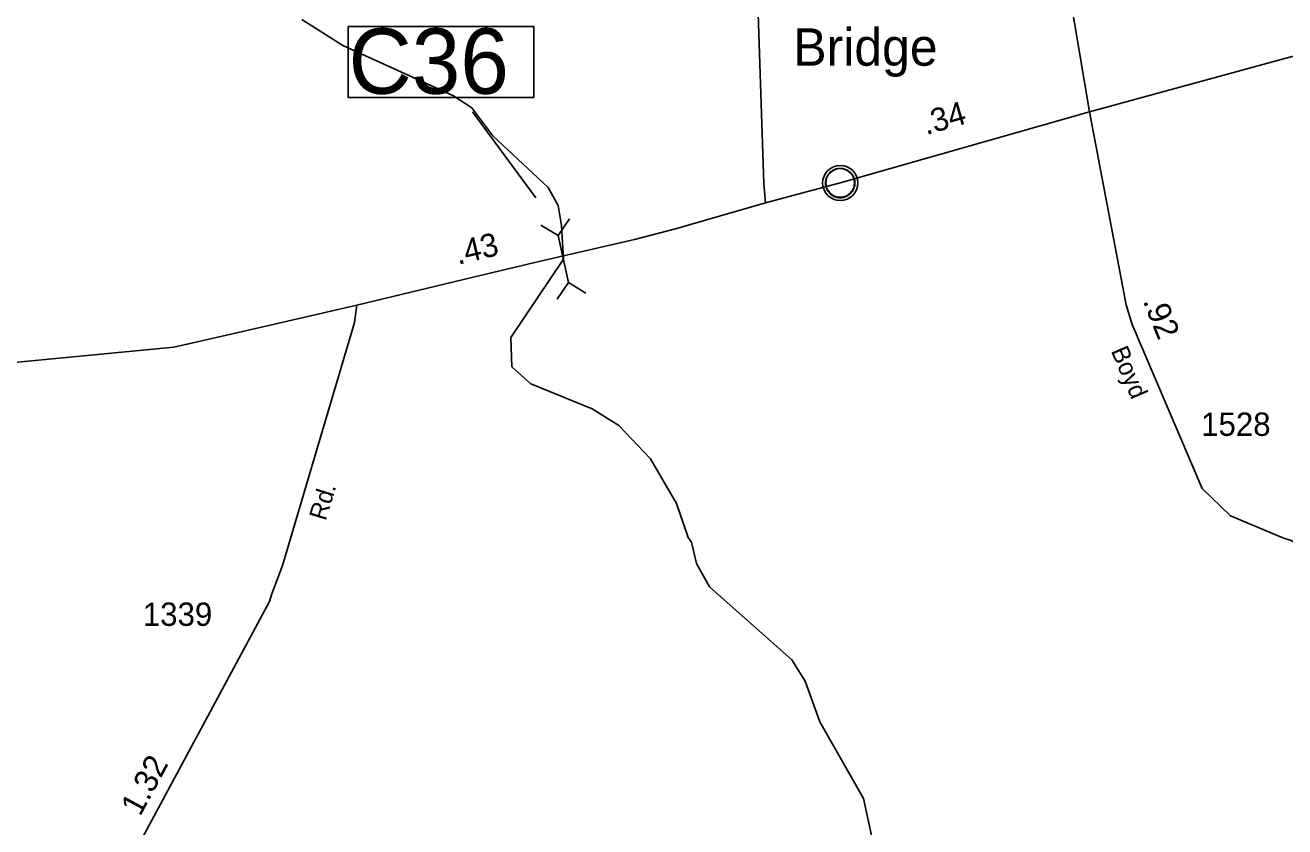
# Model space of a CAD drawing. Extents: x 2532689 to 2764727, y 536648 to 732970.
# Drawn here: x 2648911 to 2655658, y 649333 to 653624 of the extents above; entities that cross this region are included whole.
import ezdxf

# ---------------------------------------------------------------- set-up
doc = ezdxf.new("R2010")
doc.units = 0
for name, color, linetype in [('Exist Civil Demographics Community CELL', 7, 'Continuous'), ('Exist Civil Demographics Community Label', 7, 'Continuous'), ('Exist Hydrographic Creek Single Shore', 7, 'Continuous'), ('Exist Road Primary US Attributed', 7, 'Continuous'), ('Exist Road Primary US Mileage Hundredths English Label', 7, 'Continuous'), ('Exist Road Primary US Structure Culvert CELL', 7, 'Continuous'), ('Exist Road Primary US Structure Culvert Number Label', 7, 'Continuous'), ('Exist Road Secondary Mileage Hundredths English Label', 7, 'Continuous'), ('Exist Road Secondary Type 51 Attributed', 7, 'Continuous'), ('Exist Road Secondary Type 51 Label', 7, 'Continuous'), ('Exist Road Secondary Type 51 Number Label', 7, 'Continuous')]:
    doc.layers.add(name, color=color, linetype=linetype)

msp = doc.modelspace()

# ---------------------------------------------------------------- linework, layer by layer
at = {"layer": 'Exist Civil Demographics Community CELL'}
msp.add_lwpolyline([(2653199.2, 652792), (2653200.2, 652797.6), (2653201.9, 652804.2), (2653204.8, 652811.4), (2653207.8, 652817.1), (2653211.1, 652822.9), (2653214.9, 652828), (2653218.8, 652832.4), (2653223.4, 652836.9), (2653229, 652841.5), (2653234.4, 652845.2), (2653239.3, 652848.1), (2653244.3, 652850.5), (2653249.8, 652852.8), (2653255.4, 652854.6), (2653259.7, 652855.8), (2653264.6, 652856.5), (2653268.7, 652857.2), (2653275.1, 652857.5), (2653279.5, 652857.4), (2653285.2, 652857.1), (2653290.1, 652856.4), (2653295, 652855.4), (2653300, 652854), (2653305.2, 652852.1), (2653311.8, 652849.2), (2653318.1, 652845.7), (2653323.1, 652842.1), (2653328.3, 652838.1), (2653331.6, 652835), (2653335.7, 652830.6), (2653339.6, 652825.9), (2653342.7, 652821.3), (2653345.8, 652816.3), (2653348.3, 652811.1), (2653350.3, 652806.1), (2653351.9, 652801.1), (2653353.1, 652796.5), (2653354.2, 652790.5), (2653354.9, 652785.8), (2653355.1, 652779.8), (2653354.9, 652774), (2653354.4, 652768.3), (2653353.4, 652762.8), (2653351.8, 652756.6), (2653349.9, 652750.8), (2653347.6, 652745.7), (2653344.5, 652739.7), (2653341.2, 652734.4), (2653337.7, 652729.7), (2653333.5, 652725), (2653328.2, 652720), (2653323.2, 652715.9), (2653318.2, 652712.4), (2653313.8, 652709.9), (2653307, 652706.7), (2653299.9, 652704), (2653293.9, 652702.5), (2653287.3, 652701.2), (2653282.9, 652700.8), (2653278.4, 652700.5), (2653272.8, 652700.5), (2653268.6, 652700.9), (2653262.9, 652701.6), (2653257, 652703), (2653252.4, 652704.3), (2653247.2, 652706.1), (2653242.7, 652708.1), (2653238.7, 652710.4), (2653231.9, 652714.4), (2653226.3, 652718.7), (2653221.4, 652723.2), (2653217, 652728.1), (2653213.8, 652732), (2653210.8, 652736.2), (2653206.7, 652743.3), (2653205, 652746.8), (2653203.3, 652750.9), (2653200.7, 652759), (2653199.2, 652766.1), (2653198.5, 652771.3), (2653198.1, 652777.6), (2653198.1, 652782.3), (2653198.6, 652788.7)], close=True, dxfattribs=at)
for centre, radius in [((2653276.8, 652779.6), 94.3), ((2653276.5, 652779.9), 76.7)]:
    msp.add_circle(centre, radius, dxfattribs=at)
at = {"layer": 'Exist Hydrographic Creek Single Shore'}
for points in [[(2651794.1, 652372.3), (2651783.2, 652551.8), (2651765.1, 652659.4), (2651712.2, 652755.7), (2651415.1, 653032.6), (2651303.1, 653182.4), (2651201.2, 653247.3), (2650612.1, 653515.7), (2650392.1, 653654.6)], [(2653448.4, 649270), (2653401.2, 649484.8), (2653168.3, 649895.7), (2653088.3, 650112.4), (2653018.2, 650227.8), (2652576.3, 650617.1), (2652507.2, 650742.4), (2652479.3, 650856.1), (2652462.3, 650881.7), (2652400.2, 651063), (2652261.3, 651303.7), (2652091.2, 651480.7), (2651947.2, 651570.1), (2651619.1, 651704.5), (2651517.2, 651795.7), (2651513.1, 651953.1), (2651794.1, 652372.3)]]:
    msp.add_lwpolyline(points, dxfattribs=at)
at = {"layer": 'Exist Road Primary US Attributed'}
for points in [[(2654612.8, 653161.3), (2657070.5, 653833.4), (2657805.8, 654049.6), (2657837.7, 654056.5), (2658008.3, 654126.1), (2658499.5, 654345.3), (2659839.6, 654910.7), (2659932.9, 654932.9), (2660114.6, 654946.8), (2660204.4, 654959)], [(2652875.7, 652672.7), (2653276.8, 652779.6), (2654612.8, 653161.3)], [(2650688.3, 652125.8), (2651303, 652273.3), (2651641, 652354), (2651771.3, 652384.2), (2652175.3, 652477.3), (2652394.3, 652534.1), (2652875.7, 652672.7)], [(2646587, 651800.7), (2647433.1, 651714.6), (2647563.3, 651711.4), (2647680.1, 651710.8), (2648665.1, 651801.3), (2649707.1, 651901.4), (2649840.6, 651931.5), (2650199.6, 652012.8), (2650688.3, 652125.8)]]:
    msp.add_lwpolyline(points, dxfattribs=at)
at = {"layer": 'Exist Road Primary US Structure Culvert CELL'}
for p, q in [((2651827, 652587.9), (2651766.3, 652498.2)), ((2651673.5, 652554), (2651766.3, 652498.2)), ((2651821.9, 652246.4), (2651766.3, 652498.2)), ((2651761.2, 652156.8), (2651821.9, 652246.4)), ((2651914.7, 652190.6), (2651821.9, 652246.4))]:
    msp.add_line(p, q, dxfattribs=at)
at = {"layer": 'Exist Road Primary US Structure Culvert Number Label'}
msp.add_line((2651646.7, 652700.4), (2651307.5, 653160.7), dxfattribs=at)
msp.add_lwpolyline([(2650640.2, 653617.1), (2651635.7, 653617.1), (2651635.7, 653237.3), (2650640.2, 653237.3)], close=True, dxfattribs=at)
at = {"layer": 'Exist Road Secondary Type 51 Attributed'}
for points in [[(2644627, 657489.7), (2644889.9, 657447.4), (2646350.7, 657177.2), (2646965.4, 657060.9), (2648508.5, 656765.4), (2649583.3, 656565.7), (2649899.8, 656510.8), (2650148.5, 656461.3), (2650602.8, 656372), (2650781.5, 656323.5), (2650922.5, 656267.5), (2651840.2, 655889.2), (2651902.6, 655841.8), (2651943.5, 655812.7), (2651967.2, 655783.7), (2651995.2, 655756.8), (2652073.8, 655627.6), (2652824.6, 654061.9), (2652867.1, 652776), (2652875.7, 652672.7)], [(2654477.2, 653956.3), (2654612.8, 653161.3)], [(2654612.8, 653161.3), (2654807.7, 652127.4), (2654840.2, 652022), (2655215.5, 651144.1), (2655366.6, 650997.2), (2655647.5, 650879.5), (2655691.7, 650866.5), (2656452.4, 650389), (2657337.6, 649832.3)], [(2650688.3, 652125.8), (2650675.4, 652033.2), (2650289.3, 650731.4), (2650232.7, 650580), (2650219.6, 650539.8), (2648849.6, 647994.9), (2648808.3, 647952.2), (2648714.2, 647876.1), (2648162.9, 647474.4)]]:
    msp.add_lwpolyline(points, dxfattribs=at)

# ---------------------------------------------------------------- texts
at = {"layer": 'Exist Civil Demographics Community Label'}
msp.add_text('Bridge', height=200, dxfattribs=at).set_placement((2653025.5, 653407.4))
at = {"layer": 'Exist Road Primary US Mileage Hundredths English Label'}
for s, rotation, p in [('.34', 15.9458, (2653736.9, 653035.9)), ('.43', 13.51057, (2651229.5, 652341.3))]:
    msp.add_text(s, height=125, rotation=rotation, dxfattribs=at).set_placement(p)
at = {"layer": 'Exist Road Primary US Structure Culvert Number Label'}
msp.add_text('C36', height=350, dxfattribs=at).set_placement((2650643.5, 653257.1))
at = {"layer": 'Exist Road Secondary Mileage Hundredths English Label'}
for s, rotation, p in [('.92', 291.77269, (2654896.5, 652148.1)), ('1.32', 61.70528, (2649527, 649385.1))]:
    msp.add_text(s, height=125, rotation=rotation, dxfattribs=at).set_placement(p)
at = {"layer": 'Exist Road Secondary Type 51 Label'}
for s, rotation, p in [('Boyd', 293.15014, (2654725.2, 651881.4)), ('Rd.', 72.87405, (2650520.3, 650967.2))]:
    msp.add_text(s, height=95, rotation=rotation, dxfattribs=at).set_placement(p)
at = {"layer": 'Exist Road Secondary Type 51 Number Label'}
for s, p in [('1528', (2655210, 651425.8)), ('1339', (2649541.2, 650408.7))]:
    msp.add_text(s, height=125, dxfattribs=at).set_placement(p)

doc.saveas('drawing.dxf')
